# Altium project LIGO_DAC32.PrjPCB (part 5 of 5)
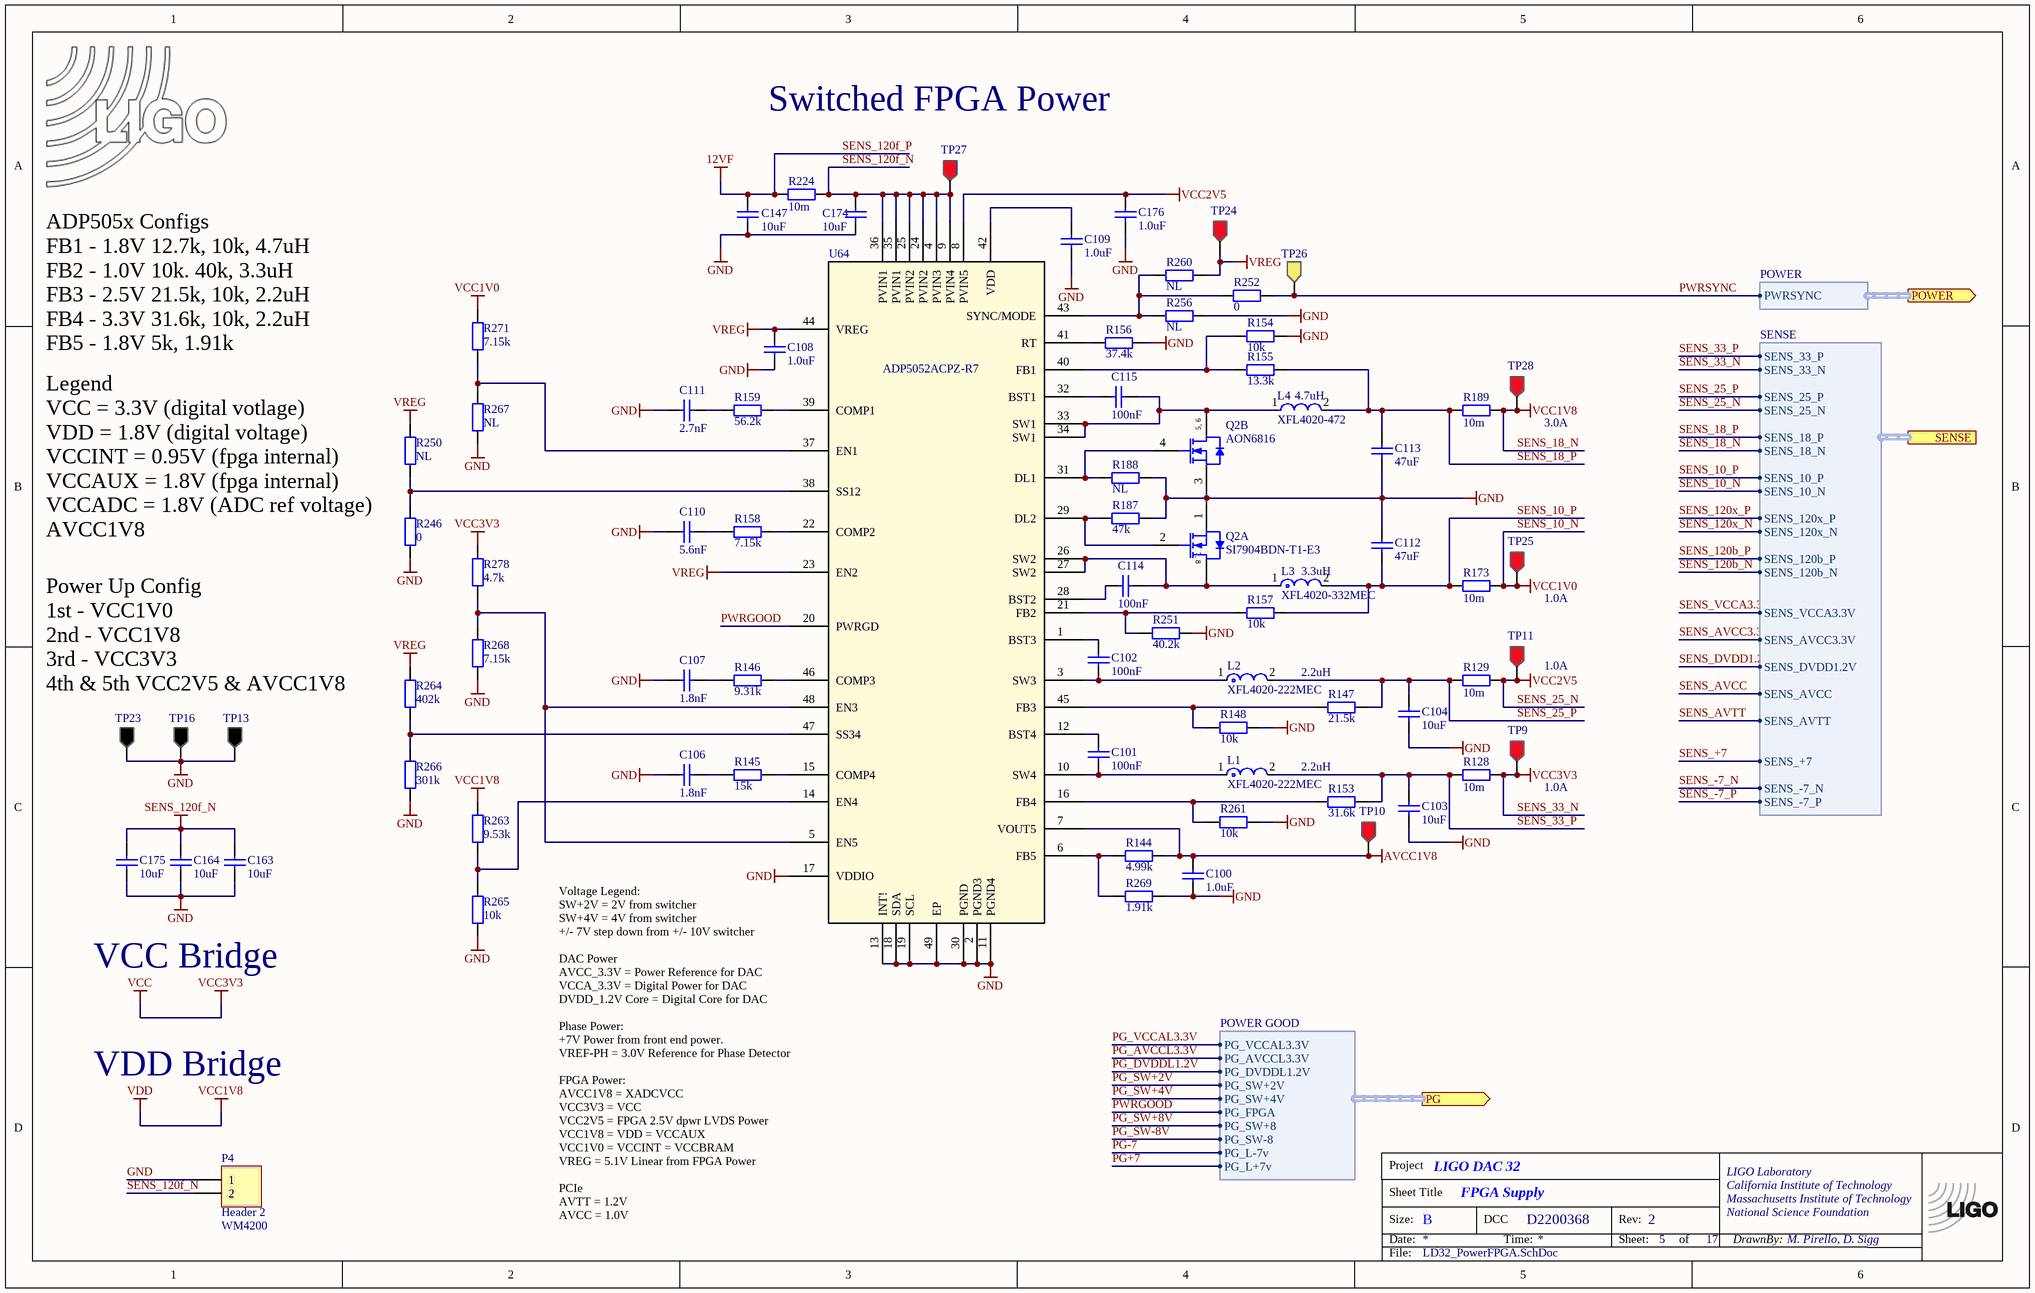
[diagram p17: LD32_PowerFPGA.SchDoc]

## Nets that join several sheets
12V: LD32_XADC (C146.1 R229.1 U81.8), LD32_PCIE_HL (5 pins)
12VA: LD32_PCIE_HL (FL2.2), LD32_Bipolar1 (FR4.1 TP37.1), LD32_Bipolar2 (FR5.1)
12VF: LD32_PCIE_HL (FL1.2), LD32_PowerFPGA (C147.1 R224.2)
+7V: LD32_Analog (5 pins), Analog/I1// (C335A.1 C415A.1 U3A.8 U19A.8), Analog/I1// (C335B.1 C415B.1 U3B.8 U19B.8), Analog/I1// (C335C.1 C415C.1 U3C.8 U19C.8), Analog/I1// (C335D.1 C415D.1 U3D.8 U19D.8), Analog/I2// (C335E.1 C415E.1 U3E.8 U19E.8), Analog/I2// (C335F.1 C415F.1 U3F.8 U19F.8), Analog/I2// (C335G.1 C415G.1 U3G.8 U19G.8), Analog/I2// (C335H.1 C415H.1 U3H.8 U19H.8), Analog/I3// (C335I.1 C415I.1 U3I.8 U19I.8), Analog/I3// (C335J.1 C415J.1 U3J.8 U19J.8), Analog/I3// (C335K.1 C415K.1 U3K.8 U19K.8), Analog/I3// (C335L.1 C415L.1 U3L.8 U19L.8), Analog/I4// (C335M.1 C415M.1 U3M.8 U19M.8), Analog/I4// (C335N.1 C415N.1 U3N.8 U19N.8), Analog/I4// (C335O.1 C415O.1 U3O.8 U19O.8), Analog/I4// (C335P.1 C415P.1 U3P.8 U19P.8), LD32_XADC (C97.2 R134.1 U63.8), LD32_PHASE (6 pins), LD32_Bipolar1 (C166.2 D8.2 R249.1 TP18.1), LD32_Linear1 (9 pins)
-7V: LD32_Analog (C479.2 U1.4), Analog/I1// (C367A.1 C447A.1 U3A.4 U19A.4), Analog/I1// (C367B.1 C447B.1 U3B.4 U19B.4), Analog/I1// (C367C.1 C447C.1 U3C.4 U19C.4), Analog/I1// (C367D.1 C447D.1 U3D.4 U19D.4), Analog/I2// (C367E.1 C447E.1 U3E.4 U19E.4), Analog/I2// (C367F.1 C447F.1 U3F.4 U19F.4), Analog/I2// (C367G.1 C447G.1 U3G.4 U19G.4), Analog/I2// (C367H.1 C447H.1 U3H.4 U19H.4), Analog/I3// (C367I.1 C447I.1 U3I.4 U19I.4), Analog/I3// (C367J.1 C447J.1 U3J.4 U19J.4), Analog/I3// (C367K.1 C447K.1 U3K.4 U19K.4), Analog/I3// (C367L.1 C447L.1 U3L.4 U19L.4), Analog/I4// (C367M.1 C447M.1 U3M.4 U19M.4), Analog/I4// (C367N.1 C447N.1 U3N.4 U19N.4), Analog/I4// (C367O.1 C447O.1 U3O.4 U19O.4), Analog/I4// (C367P.1 C447P.1 U3P.4 U19P.4), LD32_XADC (5 pins), LD32_Bipolar1 (C165.1 D9.1 R248.1 TP17.1), LD32_Linear1 (6 pins)
AGND: LD32_TOP (12 pins), LD32_Analog (12 pins), Analog/I1/ (45 pins), Analog/I1// (C335A.2 C367A.2 C415A.2 C447A.2), Analog/I1// (C335B.2 C367B.2 C415B.2 C447B.2), Analog/I1// (C335C.2 C367C.2 C415C.2 C447C.2), Analog/I1// (C335D.2 C367D.2 C415D.2 C447D.2), Analog/I2/ (45 pins), Analog/I2// (C335E.2 C367E.2 C415E.2 C447E.2), Analog/I2// (C335F.2 C367F.2 C415F.2 C447F.2), Analog/I2// (C335G.2 C367G.2 C415G.2 C447G.2), Analog/I2// (C335H.2 C367H.2 C415H.2 C447H.2), Analog/I3/ (45 pins), Analog/I3// (C335I.2 C367I.2 C415I.2 C447I.2), Analog/I3// (C335J.2 C367J.2 C415J.2 C447J.2), Analog/I3// (C335K.2 C367K.2 C415K.2 C447K.2), Analog/I3// (C335L.2 C367L.2 C415L.2 C447L.2), Analog/I4/ (45 pins), Analog/I4// (C335M.2 C367M.2 C415M.2 C447M.2), Analog/I4// (C335N.2 C367N.2 C415N.2 C447N.2), Analog/I4// (C335O.2 C367O.2 C415O.2 C447O.2), Analog/I4// (C335P.2 C367P.2 C415P.2 C447P.2), LD32_XADC (C97.1 C105.1 C181.1 U63.5), LD32_PHASE (24 pins), LD32_Power (8 pins), LD32_Bipolar1 (25 pins), LD32_Linear1 (45 pins), LD32_Bipolar2 (C144.1 C145.2 W2.2)
AVCC: FPGA_ARTIX7 (5 pins), LD32_PCIE_HL (11 pins)
AVCC1V8: LD32_XADC (C194.1 FR7.1), LD32_PowerFPGA (C100.2 R144.2 TP10.1 U64.7)
AVCC3.3V: Analog/I1/ (16 pins), Analog/I2/ (16 pins), Analog/I3/ (16 pins), Analog/I4/ (16 pins), LD32_XADC (R138.1), LD32_Linear1 (R152.1 R272.1 R273.2 TP15.1)
AVTT: FPGA_ARTIX7 (7 pins), LD32_PCIE_HL (11 pins)
BUS3.3V: LD32_PCIE_HL (C286.1 R318.2 U88.6), LD32_PCIE (P2.A9 P2.A10 P2.B8)
BUS12V: LD32_PCIE_HL (D3.1), LD32_PCIE (5 pins)
DVDD1.2V: Analog/I1/ (11 pins), Analog/I2/ (11 pins), Analog/I3/ (11 pins), Analog/I4/ (11 pins), LD32_Linear1 (R150.1 R276.2 R277.1 TP21.1)
EXTGND: LD32_PCIE_HL (6 pins), LD32_PCIE (21 pins)
GND: LD32_TOP (22 pins), LD32_FPGA (78 pins), FPGA_ARTIX7 (88 pins), LD32_XADC (5 pins), LD32_FLASH (26 pins), LD32_PHASE (14 pins), LD32_PCIE_HL (39 pins), LD32_Bipolar1 (19 pins), LD32_Bipolar2 (18 pins), LD32_PowerFPGA (45 pins)
SW+2V: LD32_PCIE_HL (L9.1 L10.1), LD32_Linear1 (R190.2 R191.2), LD32_Bipolar2 (R227.1)
SW+4V: LD32_Linear1 (R192.2 R193.2 R194.2), LD32_Bipolar2 (R228.1)
VCC: LD32_TOP (8 pins), LD32_XADC (16 pins), LD32_FLASH (C65.2 R106.1 U47.8), LD32_PHASE (16 pins), LD32_PowerFPGA (R128.1 R278.2 TP9.1)
VCC1V0: LD32_FPGA (23 pins), FPGA_ARTIX7 (17 pins), LD32_XADC (U79.2 U80.2), LD32_PowerFPGA (R173.1 R271.2 TP25.1)
VCC2V5: LD32_FPGA (7 pins), FPGA_ARTIX7 (6 pins), LD32_XADC (U60.2 U62.2), LD32_PowerFPGA (C176.2 R129.1 TP11.1 U64.8)
VCCA3.3V: Analog/I1/ (9 pins), Analog/I2/ (9 pins), Analog/I3/ (9 pins), Analog/I4/ (9 pins), LD32_Linear1 (6 pins)
VCCAUX: Analog/I1/ (10 pins), Analog/I2/ (10 pins), Analog/I3/ (10 pins), Analog/I4/ (10 pins), LD32_FPGA (53 pins), FPGA_ARTIX7 (36 pins), LD32_XADC (FR1.2 U65.2 U78.2), LD32_FLASH (20 pins), LD32_PHASE (U55.10), LD32_PCIE_HL (C268.1 U88.1), LD32_PowerFPGA (R189.1 R263.2 TP28.1)
VREG: LD32_XADC (FR3.1), LD32_PowerFPGA (7 pins)
XADCGND: LD32_FPGA (C234.1), FPGA_ARTIX7 (U45.K9), LD32_XADC (42 pins)
XADCVCC: LD32_FPGA (C234.2), FPGA_ARTIX7 (U45.K10), LD32_XADC (C193.1 C197.1 FR7.2 U87.1)
ANALOG1.A1_N: LD32_TOP (P1.80), Analog/I1// (C351B.1 R351B.2)
ANALOG1.A1_P: LD32_TOP (P1.79), Analog/I1// (C351B.2 R367B.2)
ANALOG1.A2_N: LD32_TOP (P1.68), Analog/I1// (C351A.1 R351A.2)
ANALOG1.A2_P: LD32_TOP (P1.67), Analog/I1// (C351A.2 R367A.2)
ANALOG1.A3_N: LD32_TOP (P1.78), Analog/I1// (C431B.1 R415B.2)
ANALOG1.A3_P: LD32_TOP (P1.77), Analog/I1// (C431B.2 R431B.2)
ANALOG1.A4_N: LD32_TOP (P1.66), Analog/I1// (C431A.1 R415A.2)
ANALOG1.A4_P: LD32_TOP (P1.65), Analog/I1// (C431A.2 R431A.2)
ANALOG1.A5_N: LD32_TOP (P1.76), Analog/I1// (C351C.1 R351C.2)
ANALOG1.A5_P: LD32_TOP (P1.75), Analog/I1// (C351C.2 R367C.2)
ANALOG1.A6_N: LD32_TOP (P1.72), Analog/I1// (C351D.1 R351D.2)
ANALOG1.A6_P: LD32_TOP (P1.71), Analog/I1// (C351D.2 R367D.2)
ANALOG1.A7_N: LD32_TOP (P1.74), Analog/I1// (C431C.1 R415C.2)
ANALOG1.A7_P: LD32_TOP (P1.73), Analog/I1// (C431C.2 R431C.2)
ANALOG1.A8_N: LD32_TOP (P1.70), Analog/I1// (C431D.1 R415D.2)
ANALOG1.A8_P: LD32_TOP (P1.69), Analog/I1// (C431D.2 R431D.2)
ANALOG2.A1_N: LD32_TOP (P1.62), Analog/I2// (C351F.1 R351F.2)
ANALOG2.A1_P: LD32_TOP (P1.61), Analog/I2// (C351F.2 R367F.2)
ANALOG2.A2_N: LD32_TOP (P1.50), Analog/I2// (C351E.1 R351E.2)
ANALOG2.A2_P: LD32_TOP (P1.49), Analog/I2// (C351E.2 R367E.2)
ANALOG2.A3_N: LD32_TOP (P1.60), Analog/I2// (C431F.1 R415F.2)
ANALOG2.A3_P: LD32_TOP (P1.59), Analog/I2// (C431F.2 R431F.2)
ANALOG2.A4_N: LD32_TOP (P1.48), Analog/I2// (C431E.1 R415E.2)
ANALOG2.A4_P: LD32_TOP (P1.47), Analog/I2// (C431E.2 R431E.2)
ANALOG2.A5_N: LD32_TOP (P1.58), Analog/I2// (C351G.1 R351G.2)
ANALOG2.A5_P: LD32_TOP (P1.57), Analog/I2// (C351G.2 R367G.2)
ANALOG2.A6_N: LD32_TOP (P1.54), Analog/I2// (C351H.1 R351H.2)
ANALOG2.A6_P: LD32_TOP (P1.53), Analog/I2// (C351H.2 R367H.2)
ANALOG2.A7_N: LD32_TOP (P1.56), Analog/I2// (C431G.1 R415G.2)
ANALOG2.A7_P: LD32_TOP (P1.55), Analog/I2// (C431G.2 R431G.2)
ANALOG2.A8_N: LD32_TOP (P1.52), Analog/I2// (C431H.1 R415H.2)
ANALOG2.A8_P: LD32_TOP (P1.51), Analog/I2// (C431H.2 R431H.2)
ANALOG3.A1_N: LD32_TOP (P1.44), Analog/I3// (C351J.1 R351J.2)
ANALOG3.A1_P: LD32_TOP (P1.43), Analog/I3// (C351J.2 R367J.2)
ANALOG3.A2_N: LD32_TOP (P1.32), Analog/I3// (C351I.1 R351I.2)
ANALOG3.A2_P: LD32_TOP (P1.31), Analog/I3// (C351I.2 R367I.2)
ANALOG3.A3_N: LD32_TOP (P1.42), Analog/I3// (C431J.1 R415J.2)
ANALOG3.A3_P: LD32_TOP (P1.41), Analog/I3// (C431J.2 R431J.2)
ANALOG3.A4_N: LD32_TOP (P1.30), Analog/I3// (C431I.1 R415I.2)
ANALOG3.A4_P: LD32_TOP (P1.29), Analog/I3// (C431I.2 R431I.2)
ANALOG3.A5_N: LD32_TOP (P1.40), Analog/I3// (C351K.1 R351K.2)
ANALOG3.A5_P: LD32_TOP (P1.39), Analog/I3// (C351K.2 R367K.2)
ANALOG3.A6_N: LD32_TOP (P1.36), Analog/I3// (C351L.1 R351L.2)
ANALOG3.A6_P: LD32_TOP (P1.35), Analog/I3// (C351L.2 R367L.2)
ANALOG3.A7_N: LD32_TOP (P1.38), Analog/I3// (C431K.1 R415K.2)
ANALOG3.A7_P: LD32_TOP (P1.37), Analog/I3// (C431K.2 R431K.2)
ANALOG3.A8_N: LD32_TOP (P1.34), Analog/I3// (C431L.1 R415L.2)
ANALOG3.A8_P: LD32_TOP (P1.33), Analog/I3// (C431L.2 R431L.2)
ANALOG4.A1_N: LD32_TOP (P1.26), Analog/I4// (C351N.1 R351N.2)
ANALOG4.A1_P: LD32_TOP (P1.25), Analog/I4// (C351N.2 R367N.2)
ANALOG4.A2_N: LD32_TOP (P1.14), Analog/I4// (C351M.1 R351M.2)
ANALOG4.A2_P: LD32_TOP (P1.13), Analog/I4// (C351M.2 R367M.2)
ANALOG4.A3_N: LD32_TOP (P1.24), Analog/I4// (C431N.1 R415N.2)
ANALOG4.A3_P: LD32_TOP (P1.23), Analog/I4// (C431N.2 R431N.2)
ANALOG4.A4_N: LD32_TOP (P1.12), Analog/I4// (C431M.1 R415M.2)
ANALOG4.A4_P: LD32_TOP (P1.11), Analog/I4// (C431M.2 R431M.2)
ANALOG4.A5_N: LD32_TOP (P1.22), Analog/I4// (C351O.1 R351O.2)
ANALOG4.A5_P: LD32_TOP (P1.21), Analog/I4// (C351O.2 R367O.2)
ANALOG4.A6_N: LD32_TOP (P1.18), Analog/I4// (C351P.1 R351P.2)
ANALOG4.A6_P: LD32_TOP (P1.17), Analog/I4// (C351P.2 R367P.2)
ANALOG4.A7_N: LD32_TOP (P1.20), Analog/I4// (C431O.1 R415O.2)
ANALOG4.A7_P: LD32_TOP (P1.19), Analog/I4// (C431O.2 R431O.2)
ANALOG4.A8_N: LD32_TOP (P1.16), Analog/I4// (C431P.1 R415P.2)
ANALOG4.A8_P: LD32_TOP (P1.15), Analog/I4// (C431P.2 R431P.2)
APWR1.SYNC_DIFF: FPGA_ARTIX7 (U45.Y3), LD32_Bipolar1 (R220.1 U82.19)
APWR2.SYNC_DUAL: FPGA_ARTIX7 (U45.AA1), LD32_Bipolar2 (R219.1 U83.19)
CLKE_N: LD32_TOP (R78.2 U41.6), FPGA_ARTIX7 (U45.J21)
CLKE_P: LD32_TOP (R79.2 U41.7), FPGA_ARTIX7 (U45.J20)
CLKO_N: LD32_TOP (R80.2 U42.6), FPGA_ARTIX7 (U45.L20)
CLKO_P: LD32_TOP (R81.2 U42.7), FPGA_ARTIX7 (U45.L19)
CLOCK.ACLK: FPGA_ARTIX7 (U45.B2), LD32_PHASE (U55.8)
CLOCK.ACNV: FPGA_ARTIX7 (U45.B1), LD32_PHASE (U55.6)
CLOCK.AIN: FPGA_ARTIX7 (U45.A1), LD32_PHASE (U55.7)
CLOCK.CNTROUT_N: FPGA_ARTIX7 (U45.G16), LD32_PHASE (U48.4)
CLOCK.CNTROUT_P: FPGA_ARTIX7 (U45.G15), LD32_PHASE (U48.3)
CLOCK.OSCCLK_N: FPGA_ARTIX7 (U45.K19), LD32_PHASE (R95.2 U46.6)
CLOCK.OSCCLK_P: FPGA_ARTIX7 (U45.K18), LD32_PHASE (R93.1 U46.7)
CLOCK.SYNC_N: FPGA_ARTIX7 (U45.G13), LD32_PHASE (U52.4)
CLOCK.SYNC_P: FPGA_ARTIX7 (U45.H13), LD32_PHASE (U52.3)
COM1&2: LD32_Analog (C6.1 TP3.1 U1.1 U1.2), Analog/I1// (U3A.3 U3A.5 U19A.3 U19A.5), Analog/I1// (U3B.3 U3B.5 U19B.3 U19B.5), Analog/I1// (U3C.3 U3C.5 U19C.3 U19C.5), Analog/I1// (U3D.3 U3D.5 U19D.3 U19D.5), Analog/I2// (U3E.3 U3E.5 U19E.3 U19E.5), Analog/I2// (U3F.3 U3F.5 U19F.3 U19F.5), Analog/I2// (U3G.3 U3G.5 U19G.3 U19G.5), Analog/I2// (U3H.3 U3H.5 U19H.3 U19H.5)
COM3&4: LD32_Analog (C4.1 TP2.1 U1.6 U1.7), Analog/I3// (U3I.3 U3I.5 U19I.3 U19I.5), Analog/I3// (U3J.3 U3J.5 U19J.3 U19J.5), Analog/I3// (U3K.3 U3K.5 U19K.3 U19K.5), Analog/I3// (U3L.3 U3L.5 U19L.3 U19L.5), Analog/I4// (U3M.3 U3M.5 U19M.3 U19M.5), Analog/I4// (U3N.3 U3N.5 U19N.3 U19N.5), Analog/I4// (U3O.3 U3O.5 U19O.3 U19O.5), Analog/I4// (U3P.3 U3P.5 U19P.3 U19P.5)
D1_N_: Analog/I1/ (U35A.3), Analog/I1// (C319B.2 R7B.2 R335B.1 U19B.6)
D1_N_: Analog/I2/ (U35B.3), Analog/I2// (C319F.2 R7F.2 R335F.1 U19F.6)
D1_N_: Analog/I3/ (U35C.3), Analog/I3// (C319J.2 R7J.2 R335J.1 U19J.6)
D1_N_: Analog/I4/ (U35D.3), Analog/I4// (C319N.2 R7N.2 R335N.1 U19N.6)
D1_P_: Analog/I1/ (U35A.2), Analog/I1// (C383B.2 R8B.2 R383B.1 U19B.2)
D1_P_: Analog/I2/ (U35B.2), Analog/I2// (C383F.2 R8F.2 R383F.1 U19F.2)
D1_P_: Analog/I3/ (U35C.2), Analog/I3// (C383J.2 R8J.2 R383J.1 U19J.2)
D1_P_: Analog/I4/ (U35D.2), Analog/I4// (C383N.2 R8N.2 R383N.1 U19N.2)
D2_N_: Analog/I1/ (U35A.46), Analog/I1// (C399A.2 R7A.1 R399A.1 U3A.6)
D2_N_: Analog/I2/ (U35B.46), Analog/I2// (C399E.2 R7E.1 R399E.1 U3E.6)
D2_N_: Analog/I3/ (U35C.46), Analog/I3// (C399I.2 R7I.1 R399I.1 U3I.6)
D2_N_: Analog/I4/ (U35D.46), Analog/I4// (C399M.2 R7M.1 R399M.1 U3M.6)
D2_P_: Analog/I1/ (U35A.47), Analog/I1// (C463A.2 R8A.1 R447A.1 U3A.2)
D2_P_: Analog/I2/ (U35B.47), Analog/I2// (C463E.2 R8E.1 R447E.1 U3E.2)
D2_P_: Analog/I3/ (U35C.47), Analog/I3// (C463I.2 R8I.1 R447I.1 U3I.2)
D2_P_: Analog/I4/ (U35D.47), Analog/I4// (C463M.2 R8M.1 R447M.1 U3M.2)
D3_N_: Analog/I1/ (U35A.4), Analog/I1// (C399B.2 R7B.1 R399B.1 U3B.6)
D3_N_: Analog/I2/ (U35B.4), Analog/I2// (C399F.2 R7F.1 R399F.1 U3F.6)
D3_N_: Analog/I3/ (U35C.4), Analog/I3// (C399J.2 R7J.1 R399J.1 U3J.6)
D3_N_: Analog/I4/ (U35D.4), Analog/I4// (C399N.2 R7N.1 R399N.1 U3N.6)
D3_P_: Analog/I1/ (U35A.5), Analog/I1// (C463B.2 R8B.1 R447B.1 U3B.2)
D3_P_: Analog/I2/ (U35B.5), Analog/I2// (C463F.2 R8F.1 R447F.1 U3F.2)
D3_P_: Analog/I3/ (U35C.5), Analog/I3// (C463J.2 R8J.1 R447J.1 U3J.2)
D3_P_: Analog/I4/ (U35D.5), Analog/I4// (C463N.2 R8N.1 R447N.1 U3N.2)
D4_N_: Analog/I1/ (U35A.45), Analog/I1// (C319A.2 R7A.2 R335A.1 U19A.6)
D4_N_: Analog/I2/ (U35B.45), Analog/I2// (C319E.2 R7E.2 R335E.1 U19E.6)
D4_N_: Analog/I3/ (U35C.45), Analog/I3// (C319I.2 R7I.2 R335I.1 U19I.6)
D4_N_: Analog/I4/ (U35D.45), Analog/I4// (C319M.2 R7M.2 R335M.1 U19M.6)
D4_P_: Analog/I1/ (U35A.44), Analog/I1// (C383A.2 R8A.2 R383A.1 U19A.2)
D4_P_: Analog/I2/ (U35B.44), Analog/I2// (C383E.2 R8E.2 R383E.1 U19E.2)
D4_P_: Analog/I3/ (U35C.44), Analog/I3// (C383I.2 R8I.2 R383I.1 U19I.2)
D4_P_: Analog/I4/ (U35D.44), Analog/I4// (C383M.2 R8M.2 R383M.1 U19M.2)
D5_N_: Analog/I1/ (U35A.13), Analog/I1// (C319C.2 R7C.2 R335C.1 U19C.6)
D5_N_: Analog/I2/ (U35B.13), Analog/I2// (C319G.2 R7G.2 R335G.1 U19G.6)
D5_N_: Analog/I3/ (U35C.13), Analog/I3// (C319K.2 R7K.2 R335K.1 U19K.6)
D5_N_: Analog/I4/ (U35D.13), Analog/I4// (C319O.2 R7O.2 R335O.1 U19O.6)
D5_P_: Analog/I1/ (U35A.12), Analog/I1// (C383C.2 R8C.2 R383C.1 U19C.2)
D5_P_: Analog/I2/ (U35B.12), Analog/I2// (C383G.2 R8G.2 R383G.1 U19G.2)
D5_P_: Analog/I3/ (U35C.12), Analog/I3// (C383K.2 R8K.2 R383K.1 U19K.2)
D5_P_: Analog/I4/ (U35D.12), Analog/I4// (C383O.2 R8O.2 R383O.1 U19O.2)
D6_N_: Analog/I1/ (U35A.36), Analog/I1// (C399D.2 R7D.1 R399D.1 U3D.6)
D6_N_: Analog/I2/ (U35B.36), Analog/I2// (C399H.2 R7H.1 R399H.1 U3H.6)
D6_N_: Analog/I3/ (U35C.36), Analog/I3// (C399L.2 R7L.1 R399L.1 U3L.6)
D6_N_: Analog/I4/ (U35D.36), Analog/I4// (C399P.2 R7P.1 R399P.1 U3P.6)
D6_P_: Analog/I1/ (U35A.37), Analog/I1// (C463D.2 R8D.1 R447D.1 U3D.2)
D6_P_: Analog/I2/ (U35B.37), Analog/I2// (C463H.2 R8H.1 R447H.1 U3H.2)
D6_P_: Analog/I3/ (U35C.37), Analog/I3// (C463L.2 R8L.1 R447L.1 U3L.2)
D6_P_: Analog/I4/ (U35D.37), Analog/I4// (C463P.2 R8P.1 R447P.1 U3P.2)
D7_N_: Analog/I1/ (U35A.14), Analog/I1// (C399C.2 R7C.1 R399C.1 U3C.6)
D7_N_: Analog/I2/ (U35B.14), Analog/I2// (C399G.2 R7G.1 R399G.1 U3G.6)
D7_N_: Analog/I3/ (U35C.14), Analog/I3// (C399K.2 R7K.1 R399K.1 U3K.6)
D7_N_: Analog/I4/ (U35D.14), Analog/I4// (C399O.2 R7O.1 R399O.1 U3O.6)
D7_P_: Analog/I1/ (U35A.15), Analog/I1// (C463C.2 R8C.1 R447C.1 U3C.2)
D7_P_: Analog/I2/ (U35B.15), Analog/I2// (C463G.2 R8G.1 R447G.1 U3G.2)
D7_P_: Analog/I3/ (U35C.15), Analog/I3// (C463K.2 R8K.1 R447K.1 U3K.2)
D7_P_: Analog/I4/ (U35D.15), Analog/I4// (C463O.2 R8O.1 R447O.1 U3O.2)
D8_N_: Analog/I1/ (U35A.35), Analog/I1// (C319D.2 R7D.2 R335D.1 U19D.6)
D8_N_: Analog/I2/ (U35B.35), Analog/I2// (C319H.2 R7H.2 R335H.1 U19H.6)
D8_N_: Analog/I3/ (U35C.35), Analog/I3// (C319L.2 R7L.2 R335L.1 U19L.6)
D8_N_: Analog/I4/ (U35D.35), Analog/I4// (C319P.2 R7P.2 R335P.1 U19P.6)
D8_P_: Analog/I1/ (U35A.34), Analog/I1// (C383D.2 R8D.2 R383D.1 U19D.2)
D8_P_: Analog/I2/ (U35B.34), Analog/I2// (C383H.2 R8H.2 R383H.1 U19H.2)
D8_P_: Analog/I3/ (U35C.34), Analog/I3// (C383L.2 R8L.2 R383L.1 U19L.2)
D8_P_: Analog/I4/ (U35D.34), Analog/I4// (C383P.2 R8P.2 R383P.1 U19P.2)
DAC1.BCLK: Analog/I1/ (U35A.60), FPGA_ARTIX7 (U45.AA20)
DAC1.D0: Analog/I1/ (U35A.58), FPGA_ARTIX7 (U45.W20)
DAC1.D1: Analog/I1/ (U35A.57), FPGA_ARTIX7 (U45.AB21)
DAC1.D2: Analog/I1/ (U35A.56), FPGA_ARTIX7 (U45.AB22)
DAC1.D3: Analog/I1/ (U35A.55), FPGA_ARTIX7 (U45.AA21)
DAC1.DCLK_N: Analog/I1/ (R319A.1 U89A.4), FPGA_ARTIX7 (U45.M22)
DAC1.DCLK_P: Analog/I1/ (R319A.2 U89A.3), FPGA_ARTIX7 (U45.N22)
DAC1.LRCK: Analog/I1/ (U35A.59), FPGA_ARTIX7 (U45.AB20)
DAC1.RST: Analog/I1/ (R55A.2 R56A.1 U35A.8), FPGA_ARTIX7 (U45.AA19)
DAC1.SCL: Analog/I1/ (R41A.1 U35A.22), FPGA_ARTIX7 (U45.Y18)
DAC1.SDA: Analog/I1/ (R42A.1 U35A.21), FPGA_ARTIX7 (U45.AA18)
DAC2.BCLK: Analog/I2/ (U35B.60), FPGA_ARTIX7 (U45.W22)
DAC2.D0: Analog/I2/ (U35B.58), FPGA_ARTIX7 (U45.U20)
DAC2.D1: Analog/I2/ (U35B.57), FPGA_ARTIX7 (U45.T21)
DAC2.D2: Analog/I2/ (U35B.56), FPGA_ARTIX7 (U45.R19)
DAC2.D3: Analog/I2/ (U35B.55), FPGA_ARTIX7 (U45.P20)
DAC2.DCLK_N: Analog/I2/ (R319B.1 U89B.4), FPGA_ARTIX7 (U45.L21)
DAC2.DCLK_P: Analog/I2/ (R319B.2 U89B.3), FPGA_ARTIX7 (U45.M21)
DAC2.LRCK: Analog/I2/ (U35B.59), FPGA_ARTIX7 (U45.V20)
DAC2.RST: Analog/I2/ (R55B.2 R56B.1 U35B.8), FPGA_ARTIX7 (U45.W21)
DAC2.SCL: Analog/I2/ (R41B.1 U35B.22), FPGA_ARTIX7 (U45.Y22)
DAC2.SDA: Analog/I2/ (R42B.1 U35B.21), FPGA_ARTIX7 (U45.Y21)
DAC3.BCLK: Analog/I3/ (U35C.60), FPGA_ARTIX7 (U45.F20)
DAC3.D0: Analog/I3/ (U35C.58), FPGA_ARTIX7 (U45.D22)
DAC3.D1: Analog/I3/ (U35C.57), FPGA_ARTIX7 (U45.D21)
DAC3.D2: Analog/I3/ (U35C.56), FPGA_ARTIX7 (U45.C22)
DAC3.D3: Analog/I3/ (U35C.55), FPGA_ARTIX7 (U45.B21)
DAC3.DCLK_N: Analog/I3/ (R319C.1 U89C.4), FPGA_ARTIX7 (U45.K22)
DAC3.DCLK_P: Analog/I3/ (R319C.2 U89C.3), FPGA_ARTIX7 (U45.K21)
DAC3.LRCK: Analog/I3/ (U35C.59), FPGA_ARTIX7 (U45.E21)
DAC3.RST: Analog/I3/ (R55C.2 R56C.1 U35C.8), FPGA_ARTIX7 (U45.F21)
DAC3.SCL: Analog/I3/ (R41C.1 U35C.22), FPGA_ARTIX7 (U45.G22)
DAC3.SDA: Analog/I3/ (R42C.1 U35C.21), FPGA_ARTIX7 (U45.G21)
DAC4.BCLK: Analog/I4/ (U35D.60), FPGA_ARTIX7 (U45.C20)
DAC4.D0: Analog/I4/ (U35D.58), FPGA_ARTIX7 (U45.A19)
DAC4.D1: Analog/I4/ (U35D.57), FPGA_ARTIX7 (U45.B18)
DAC4.D2: Analog/I4/ (U35D.56), FPGA_ARTIX7 (U45.A18)
DAC4.D3: Analog/I4/ (U35D.55), FPGA_ARTIX7 (U45.B17)
DAC4.DCLK_N: Analog/I4/ (R319D.1 U89D.4), FPGA_ARTIX7 (U45.H22)
DAC4.DCLK_P: Analog/I4/ (R319D.2 U89D.3), FPGA_ARTIX7 (U45.J22)
DAC4.LRCK: Analog/I4/ (U35D.59), FPGA_ARTIX7 (U45.C19)
DAC4.RST: Analog/I4/ (R55D.2 R56D.1 U35D.8), FPGA_ARTIX7 (U45.A21)
DAC4.SCL: Analog/I4/ (R41D.1 U35D.22), FPGA_ARTIX7 (U45.B20)
DAC4.SDA: Analog/I4/ (R42D.1 U35D.21), FPGA_ARTIX7 (U45.B22)
EXT.TRIGout_N: LD32_TOP (R76.1 R86.1 U43.2), FPGA_ARTIX7 (U45.G20)
EXT.TRIGout_P: LD32_TOP (R77.1 R86.2 U43.3), FPGA_ARTIX7 (U45.H20)
EXTCLK.CAUX_N: FPGA_ARTIX7 (U45.H19), LD32_FLASH (R101.2 U47.6)
EXTCLK.CAUX_P: FPGA_ARTIX7 (U45.J19), LD32_FLASH (R104.2 U47.7)
LED_A: LD32_FPGA (Q9.1 R290.1), FPGA_ARTIX7 (U45.V19)
LED_B: LD32_FPGA (Q8.1 R288.1), FPGA_ARTIX7 (U45.V18)
LED_C: LD32_FPGA (Q7.1 R285.1), FPGA_ARTIX7 (U45.V17)
LED_D: LD32_FPGA (Q6.1 R280.1), FPGA_ARTIX7 (U45.U18)
LED_PG: LD32_FPGA (Q10.1 R295.1), FPGA_ARTIX7 (U45.W19)
PCIE.PCIE_CLK_N: FPGA_ARTIX7 (U45.E6), LD32_PCIE_HL (C284.2)
PCIE.PCIE_CLK_P: FPGA_ARTIX7 (U45.F6), LD32_PCIE_HL (C285.2)
PCIE.PCIE_PERST: FPGA_ARTIX7 (U45.A15), LD32_PCIE_HL (U88.3)
PCIE.PCIE_PWRGD: FPGA_ARTIX7 (U45.T1), LD32_PCIE_HL (U70.5 U71.5)
PCIE.PCIE_RX0_N: FPGA_ARTIX7 (U45.B8), LD32_PCIE (P2.B15)
PCIE.PCIE_RX0_P: FPGA_ARTIX7 (U45.A8), LD32_PCIE (P2.B14)
PCIE.PCIE_RX1_N: FPGA_ARTIX7 (U45.D11), LD32_PCIE (P2.B20)
PCIE.PCIE_RX1_P: FPGA_ARTIX7 (U45.C11), LD32_PCIE (P2.B19)
PCIE.PCIE_RX2_N: FPGA_ARTIX7 (U45.B10), LD32_PCIE (P2.B24)
PCIE.PCIE_RX2_P: FPGA_ARTIX7 (U45.A10), LD32_PCIE (P2.B23)
PCIE.PCIE_RX3_N: FPGA_ARTIX7 (U45.D9), LD32_PCIE (P2.B28)
PCIE.PCIE_RX3_P: FPGA_ARTIX7 (U45.C9), LD32_PCIE (P2.B27)
PCIE.PCIE_TX0_N: FPGA_ARTIX7 (U45.B4), LD32_PCIE_HL (C280.2)
PCIE.PCIE_TX0_P: FPGA_ARTIX7 (U45.A4), LD32_PCIE_HL (C282.2)
PCIE.PCIE_TX1_N: FPGA_ARTIX7 (U45.D5), LD32_PCIE_HL (C278.2)
PCIE.PCIE_TX1_P: FPGA_ARTIX7 (U45.C5), LD32_PCIE_HL (C279.2)
PCIE.PCIE_TX2_N: FPGA_ARTIX7 (U45.B6), LD32_PCIE_HL (C276.2)
PCIE.PCIE_TX2_P: FPGA_ARTIX7 (U45.A6), LD32_PCIE_HL (C277.2)
PCIE.PCIE_TX3_N: FPGA_ARTIX7 (U45.D7), LD32_PCIE_HL (C274.2)
PCIE.PCIE_TX3_P: FPGA_ARTIX7 (U45.C7), LD32_PCIE_HL (C275.2)
PER0_N: LD32_PCIE_HL (C280.1), LD32_PCIE (P2.A17)
PER0_P: LD32_PCIE_HL (C282.1), LD32_PCIE (P2.A16)
PER1_N: LD32_PCIE_HL (C278.1), LD32_PCIE (P2.A22)
PER1_P: LD32_PCIE_HL (C279.1), LD32_PCIE (P2.A21)
PER2_N: LD32_PCIE_HL (C276.1), LD32_PCIE (P2.A26)
PER2_P: LD32_PCIE_HL (C277.1), LD32_PCIE (P2.A25)
PER3_N: LD32_PCIE_HL (C274.1), LD32_PCIE (P2.A30)
PER3_P: LD32_PCIE_HL (C275.1), LD32_PCIE (P2.A29)
PERST#: LD32_PCIE_HL (R317.1), LD32_PCIE (P2.A11)
POWER.PWRSYNC: FPGA_ARTIX7 (U45.AB2), LD32_PowerFPGA (R252.2 TP26.1)
REFCLK_N: LD32_PCIE_HL (C284.1), LD32_PCIE (P2.A14)
REFCLK_P: LD32_PCIE_HL (C285.1), LD32_PCIE (P2.A13)
SENSE.SENS_10_P: LD32_XADC (U79.3 U80.3), LD32_PowerFPGA (C112.1 L3.2 R157.2 R173.2)
SENSE.SENS_18_P: LD32_XADC (U65.3 U78.3), LD32_PowerFPGA (C113.2 L4.2 R155.2 R189.2)
SENSE.SENS_25_P: LD32_XADC (U60.3 U62.3), LD32_PowerFPGA (C104.2 L2.2 R129.2 R147.2)
SENSE.SENS_33_P: LD32_XADC (U59.3 U61.3), LD32_PowerFPGA (C103.2 L1.2 R128.2 R153.2)
SENSE.SENS_120b_N: LD32_XADC (R197.2), LD32_PCIE_HL (R199.2)
SENSE.SENS_120b_P: LD32_XADC (R200.2), LD32_PCIE_HL (R199.3)
SENSE.SENS_120x_N: LD32_XADC (R198.1), LD32_PCIE_HL (R222.3)
SENSE.SENS_120x_P: LD32_XADC (R223.1), LD32_PCIE_HL (R222.2)
SENSE.SENS_+7: LD32_XADC (R257.1), LD32_Bipolar1 (R181.2 U68.6 U69.6)
SENSE.SENS_-7_N: LD32_XADC (R247.1), LD32_Bipolar1 (R165.1 R166.1 R180.1 R248.2)
SENSE.SENS_AVCC: LD32_XADC (R259.1), LD32_PCIE_HL (R183.2 U71.6)
SENSE.SENS_AVCC3.3V: LD32_XADC (R255.1), LD32_Linear1 (R179.1 U75.6 U76.6)
SENSE.SENS_AVTT: LD32_XADC (R258.1), LD32_PCIE_HL (R182.2 U70.6)
SENSE.SENS_DVDD1.2V: LD32_XADC (R253.1), LD32_Linear1 (R177.1 U72.6 U73.6)
SENSE.SENS_VCCA3.3V: LD32_XADC (R254.1), LD32_Linear1 (R178.1 U74.6)
SQSPI.EMCLK_EN: FPGA_ARTIX7 (U45.U21), LD32_FLASH (R96.2 Y1.1)
SQSPI.PUDC_B: FPGA_ARTIX7 (U45.U22), LD32_FLASH (R70.1 R71.1)
SQSPI.QSPI_CS: FPGA_ARTIX7 (U45.T19), LD32_FLASH (R85.2 U39.7 U40.1)
SQSPI.QSPI_DQ0: FPGA_ARTIX7 (U45.P22), LD32_FLASH (R83.2)
SQSPI.QSPI_DQ1: FPGA_ARTIX7 (U45.R22), LD32_FLASH (R89.2)
SQSPI.QSPI_DQ2: FPGA_ARTIX7 (U45.P21), LD32_FLASH (R84.2)
SQSPI.QSPI_DQ3: FPGA_ARTIX7 (U45.R21), LD32_FLASH (R72.2)
SQSPI.QSPI_EMCLK: FPGA_ARTIX7 (U45.V22), LD32_FLASH (Y1.3)
SW1: LD32_TOP (S1.16), FPGA_ARTIX7 (U45.AA5)
SW2: LD32_TOP (S1.15), FPGA_ARTIX7 (U45.AB5)
SW3: LD32_TOP (S1.14), FPGA_ARTIX7 (U45.AA6)
SW4: LD32_TOP (S1.13), FPGA_ARTIX7 (U45.AB6)
SW5: LD32_TOP (S1.12), FPGA_ARTIX7 (U45.AB7)
SW6: LD32_TOP (S1.11), FPGA_ARTIX7 (U45.AA8)
SW7: LD32_TOP (S1.10), FPGA_ARTIX7 (U45.AB8)
SW8: LD32_TOP (S1.9), FPGA_ARTIX7 (U45.Y9)
XADC_N: LD32_XADC (C187.2 C233.1 R283.2), LD32_FLASH (U45.M9)
XADC_P: LD32_XADC (C187.1 C233.2 R282.2), LD32_FLASH (U45.L10)
XADC_REF_N: LD32_XADC (W3.2), LD32_FLASH (U45.L9)
XADC_REF_P: LD32_XADC (C203.1 R136.1 U87.2), LD32_FLASH (U45.M10)
XMUX0: FPGA_ARTIX7 (U45.K1), LD32_XADC (U56.12)
XMUX1: FPGA_ARTIX7 (U45.L1), LD32_XADC (U56.11)
XMUX2: FPGA_ARTIX7 (U45.M1), LD32_XADC (U56.10)
XMUX3: FPGA_ARTIX7 (U45.J1), LD32_XADC (U56.13)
